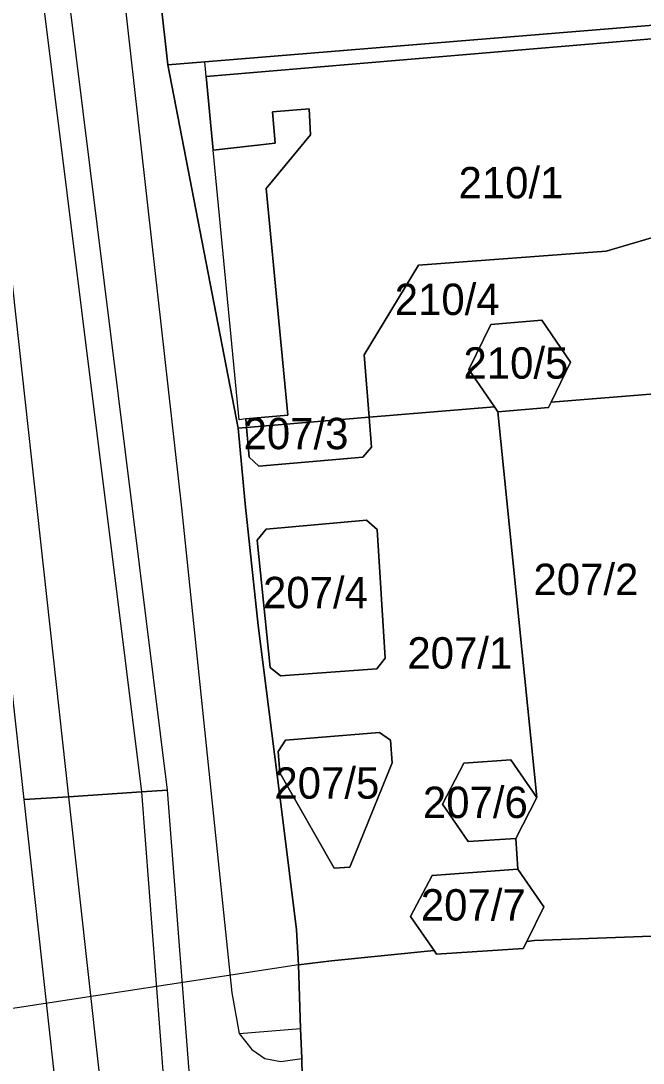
# Model space of a CAD drawing. Extents: x -263423 to -261326, y -1240067 to -1237864.
# Drawn here: x -263160.1 to -263120.4, y -1239967.1 to -1239900.6 of the extents above; entities that cross this region are included whole.
import ezdxf

# ---------------------------------------------------------------- set-up
doc = ezdxf.new("R2010")
doc.units = 0
for name, color, linetype in [('body_kn', 7, 'Continuous'), ('kladpar_druhypozemkov', 7, 'Continuous'), ('kladpar_hranice', 7, 'Continuous'), ('kladpar_parcelnecisla', 7, 'Continuous'), ('kladpar_plochy', 7, 'Continuous'), ('linie', 7, 'Continuous'), ('tarchy_linie', 7, 'Continuous'), ('zappar_hrandruhpozemk', 7, 'Continuous')]:
    doc.layers.add(name, color=color, linetype=linetype)

msp = doc.modelspace()

# ---------------------------------------------------------------- linework, layer by layer
at = {"layer": 'body_kn'}
for p, q in [((-263150.73, -1239903.4), (-263150.73, -1239903.4)), ((-263150.73, -1239903.4), (-263150.73, -1239903.4)), ((-263148.38, -1239903.21), (-263148.38, -1239903.21)), ((-263148.29, -1239904.14), (-263148.29, -1239904.14)), ((-263148.29, -1239904.14), (-263148.29, -1239904.14)), ((-263141.71, -1239906.2), (-263141.71, -1239906.2)), ((-263144.05, -1239906.4), (-263144.05, -1239906.4)), ((-263141.63, -1239907.86), (-263141.63, -1239907.86)), ((-263147.84, -1239908.83), (-263147.84, -1239908.83)), ((-263143.88, -1239908.39), (-263143.88, -1239908.39)), ((-263144.45, -1239911.29), (-263144.45, -1239911.29)), ((-263122.76, -1239915.27), (-263122.76, -1239915.27)), ((-263134.75, -1239916.18), (-263134.75, -1239916.18)), ((-263130.12, -1239919.95), (-263130.12, -1239919.95)), ((-263126.87, -1239919.67), (-263126.87, -1239919.67)), ((-263138.21, -1239921.88), (-263138.21, -1239921.88)), ((-263131.54, -1239922.83), (-263131.54, -1239922.83)), ((-263125.04, -1239922.35), (-263125.04, -1239922.35)), ((-263126.28, -1239924.91), (-263126.28, -1239924.91)), ((-263129.9, -1239925.21), (-263129.9, -1239925.21)), ((-263129.68, -1239925.52), (-263129.68, -1239925.52)), ((-263129.68, -1239925.52), (-263129.68, -1239925.52)), ((-263126.44, -1239925.26), (-263126.44, -1239925.26)), ((-263146.19, -1239926.04), (-263146.19, -1239926.04)), ((-263145.76, -1239925.98), (-263145.76, -1239925.98)), ((-263145.76, -1239925.98), (-263145.76, -1239925.98)), ((-263143.07, -1239925.74), (-263143.07, -1239925.74)), ((-263137.88, -1239925.87), (-263137.88, -1239925.87)), ((-263137.88, -1239925.87), (-263137.88, -1239925.87)), ((-263146.25, -1239926.56), (-263146.25, -1239926.56)), ((-263146.25, -1239926.56), (-263146.25, -1239926.56)), ((-263145.72, -1239926.52), (-263145.72, -1239926.52)), ((-263137.73, -1239927.77), (-263137.73, -1239927.77)), ((-263145.54, -1239928.42), (-263145.54, -1239928.42)), ((-263138.29, -1239928.41), (-263138.29, -1239928.41)), ((-263144.93, -1239928.99), (-263144.93, -1239928.99)), ((-263145.8, -1239931.39), (-263145.8, -1239931.39)), ((-263149.86, -1239931.65), (-263149.86, -1239931.65)), ((-263138.06, -1239932.44), (-263138.06, -1239932.44)), ((-263144.47, -1239933.01), (-263144.47, -1239933.01)), ((-263137.38, -1239933.02), (-263137.38, -1239933.02)), ((-263145.03, -1239933.7), (-263145.03, -1239933.7)), ((-263144.96, -1239939.15), (-263144.96, -1239939.15)), ((-263136.87, -1239941.24), (-263136.87, -1239941.24)), ((-263136.87, -1239941.24), (-263136.87, -1239941.24)), ((-263144.21, -1239941.83), (-263144.21, -1239941.83)), ((-263137.39, -1239941.92), (-263137.39, -1239941.92)), ((-263143.54, -1239942.37), (-263143.54, -1239942.37)), ((-263137.23, -1239945.98), (-263137.23, -1239945.98)), ((-263143.23, -1239946.46), (-263143.23, -1239946.46)), ((-263136.53, -1239946.46), (-263136.53, -1239946.46)), ((-263143.7, -1239947.18), (-263143.7, -1239947.18)), ((-263136.42, -1239947.91), (-263136.42, -1239947.91)), ((-263131.84, -1239947.94), (-263131.84, -1239947.94)), ((-263128.86, -1239947.72), (-263128.86, -1239947.72)), ((-263143.58, -1239948.55), (-263143.58, -1239948.55)), ((-263157.06, -1239950.07), (-263157.06, -1239950.07)), ((-263157.06, -1239950.07), (-263157.06, -1239950.07)), ((-263152.42, -1239949.77), (-263152.42, -1239949.77)), ((-263152.42, -1239949.77), (-263152.42, -1239949.77)), ((-263150.78, -1239949.66), (-263150.78, -1239949.66)), ((-263127.19, -1239950.13), (-263127.19, -1239950.13)), ((-263159.9, -1239950.26), (-263159.9, -1239950.26)), ((-263133.22, -1239950.55), (-263133.22, -1239950.55)), ((-263143.42, -1239951.37), (-263143.42, -1239951.37)), ((-263128.54, -1239952.74), (-263128.54, -1239952.74)), ((-263128.54, -1239952.74), (-263128.54, -1239952.74)), ((-263131.57, -1239952.92), (-263131.57, -1239952.92)), ((-263140.12, -1239954.63), (-263140.12, -1239954.63)), ((-263139.12, -1239954.57), (-263139.12, -1239954.57)), ((-263139.12, -1239954.57), (-263139.12, -1239954.57)), ((-263128.4, -1239954.7), (-263128.4, -1239954.7)), ((-263133.88, -1239955.09), (-263133.88, -1239955.09)), ((-263126.75, -1239957.09), (-263126.75, -1239957.09)), ((-263126.75, -1239957.09), (-263126.75, -1239957.09)), ((-263135.25, -1239957.71), (-263135.25, -1239957.71)), ((-263142.52, -1239958.56), (-263142.52, -1239958.56)), ((-263127.83, -1239959.3), (-263127.83, -1239959.3)), ((-263127.34, -1239959.25), (-263127.34, -1239959.25)), ((-263133.75, -1239959.88), (-263133.75, -1239959.88)), ((-263133.59, -1239960.12), (-263133.59, -1239960.12)), ((-263128.06, -1239959.75), (-263128.06, -1239959.75)), ((-263142.39, -1239960.79), (-263142.39, -1239960.79)), ((-263140.3, -1239960.53), (-263140.3, -1239960.53)), ((-263146.64, -1239962.57), (-263146.64, -1239962.57)), ((-263146.19, -1239965.18), (-263146.19, -1239965.18)), ((-263146.19, -1239965.18), (-263146.19, -1239965.18)), ((-263142.26, -1239964.86), (-263142.26, -1239964.86)), ((-263145.37, -1239966.2), (-263145.37, -1239966.2)), ((-263144.54, -1239966.77), (-263144.54, -1239966.77)), ((-263142.19, -1239966.77), (-263142.19, -1239966.77)), ((-263143.52, -1239966.96), (-263143.52, -1239966.96))]:
    msp.add_line(p, q, dxfattribs=at)
at = {"layer": 'kladpar_druhypozemkov'}
for p, q in [((-263128.82, -1239910.13), (-263128.82, -1239910.13)), ((-263132.19, -1239917.97), (-263132.19, -1239917.97)), ((-263128.51, -1239921.59), (-263128.51, -1239921.59)), ((-263141.62, -1239926.61), (-263141.62, -1239926.61)), ((-263123.27, -1239935.24), (-263123.27, -1239935.24)), ((-263140.81, -1239935.63), (-263140.81, -1239935.63)), ((-263131.75, -1239940.11), (-263131.75, -1239940.11)), ((-263140, -1239948.19), (-263140, -1239948.19)), ((-263130.59, -1239949.77), (-263130.59, -1239949.77)), ((-263130.77, -1239956.39), (-263130.77, -1239956.39))]:
    msp.add_line(p, q, dxfattribs=at)
at = {"layer": 'kladpar_hranice'}
for points in [[(-263160.1, -1239830.46), (-263160.09, -1239840), (-263159.96, -1239841.97), (-263159.77, -1239843.43), (-263157.36, -1239843.24), (-263154.97, -1239865.49), (-263150.73, -1239903.4), (-263146.25, -1239926.56), (-263145.8, -1239931.39), (-263144.96, -1239939.15), (-263143.42, -1239951.37), (-263142.52, -1239958.56), (-263142.39, -1239960.79), (-263142.26, -1239964.86), (-263142.19, -1239966.77), (-263141.99, -1239976.76)], [(-263109.71, -1239861.4), (-263104.15, -1239861.04), (-263104.09, -1239861.55), (-263103.51, -1239866.79), (-263103.48, -1239867.04), (-263117.01, -1239868.18), (-263116.53, -1239872.27), (-263114.41, -1239890.35), (-263113.94, -1239894.4), (-263113.26, -1239900.34), (-263148.38, -1239903.21), (-263150.73, -1239903.4), (-263154.97, -1239865.49), (-263140.37, -1239864.09), (-263109.71, -1239861.4)], [(-263150.73, -1239903.4), (-263148.38, -1239903.21), (-263113.26, -1239900.34)], [(-263113.57, -1239901.21), (-263148.29, -1239904.14), (-263147.84, -1239908.83), (-263143.88, -1239908.39), (-263144.05, -1239906.4), (-263141.71, -1239906.2), (-263141.63, -1239907.86), (-263144.45, -1239911.29), (-263143.07, -1239925.74), (-263145.76, -1239925.98), (-263145.72, -1239926.52), (-263146.25, -1239926.56), (-263150.73, -1239903.4)], [(-263137.88, -1239925.87), (-263145.72, -1239926.52), (-263145.76, -1239925.98), (-263143.07, -1239925.74), (-263144.45, -1239911.29), (-263141.63, -1239907.86), (-263141.71, -1239906.2), (-263144.05, -1239906.4), (-263143.88, -1239908.39), (-263147.84, -1239908.83), (-263148.29, -1239904.14), (-263113.57, -1239901.21), (-263113.38, -1239902.45), (-263113.51, -1239902.94), (-263119.88, -1239914.43), (-263122.76, -1239915.27), (-263134.75, -1239916.18), (-263138.21, -1239921.88), (-263137.88, -1239925.87)], [(-263119.15, -1239924.33), (-263126.28, -1239924.91), (-263125.04, -1239922.35), (-263126.87, -1239919.67), (-263130.12, -1239919.95), (-263131.54, -1239922.83), (-263129.9, -1239925.21), (-263137.88, -1239925.87), (-263138.21, -1239921.88), (-263134.75, -1239916.18), (-263122.76, -1239915.27), (-263119.88, -1239914.43)], [(-263129.68, -1239925.52), (-263129.9, -1239925.21), (-263131.54, -1239922.83), (-263130.12, -1239919.95), (-263126.87, -1239919.67), (-263125.04, -1239922.35), (-263126.28, -1239924.91), (-263126.44, -1239925.26), (-263129.68, -1239925.52)], [(-263107.84, -1239958.51), (-263127.34, -1239959.25), (-263127.83, -1239959.3), (-263126.75, -1239957.09), (-263128.4, -1239954.7), (-263128.54, -1239952.74), (-263127.19, -1239950.13), (-263129.68, -1239925.52), (-263126.44, -1239925.26), (-263126.28, -1239924.91), (-263119.15, -1239924.33)], [(-263146.25, -1239926.56), (-263145.72, -1239926.52), (-263145.54, -1239928.42), (-263144.93, -1239928.99), (-263138.29, -1239928.41), (-263137.73, -1239927.77), (-263137.88, -1239925.87), (-263129.9, -1239925.21), (-263129.68, -1239925.52), (-263127.19, -1239950.13), (-263128.86, -1239947.72), (-263131.84, -1239947.94), (-263133.22, -1239950.55), (-263131.57, -1239952.92), (-263128.54, -1239952.74), (-263128.4, -1239954.7), (-263133.88, -1239955.09), (-263135.25, -1239957.71), (-263133.75, -1239959.88), (-263140.3, -1239960.53), (-263142.39, -1239960.79), (-263142.52, -1239958.56)], [(-263137.88, -1239925.87), (-263137.73, -1239927.77), (-263138.29, -1239928.41), (-263144.93, -1239928.99), (-263145.54, -1239928.42), (-263145.72, -1239926.52), (-263137.88, -1239925.87)], [(-263144.96, -1239939.15), (-263145.8, -1239931.39), (-263146.25, -1239926.56)], [(-263136.87, -1239941.24), (-263137.39, -1239941.92), (-263143.54, -1239942.37), (-263144.21, -1239941.83), (-263145.03, -1239933.7), (-263144.47, -1239933.01), (-263138.06, -1239932.44), (-263137.38, -1239933.02), (-263136.87, -1239941.24)], [(-263144.21, -1239941.83), (-263143.54, -1239942.37), (-263137.39, -1239941.92), (-263136.87, -1239941.24), (-263137.38, -1239933.02), (-263138.06, -1239932.44), (-263144.47, -1239933.01), (-263145.03, -1239933.7), (-263144.21, -1239941.83)], [(-263142.52, -1239958.56), (-263143.42, -1239951.37), (-263144.96, -1239939.15)], [(-263139.12, -1239954.57), (-263140.12, -1239954.63), (-263143.58, -1239948.55), (-263143.7, -1239947.18), (-263143.23, -1239946.46), (-263137.23, -1239945.98), (-263136.53, -1239946.46), (-263136.42, -1239947.91), (-263139.12, -1239954.57)], [(-263139.12, -1239954.57), (-263136.42, -1239947.91), (-263136.53, -1239946.46), (-263137.23, -1239945.98), (-263143.23, -1239946.46), (-263143.7, -1239947.18), (-263143.58, -1239948.55), (-263140.12, -1239954.63), (-263139.12, -1239954.57)], [(-263128.54, -1239952.74), (-263131.57, -1239952.92), (-263133.22, -1239950.55), (-263131.84, -1239947.94), (-263128.86, -1239947.72), (-263127.19, -1239950.13), (-263128.54, -1239952.74)], [(-263126.75, -1239957.09), (-263127.83, -1239959.3), (-263128.06, -1239959.75), (-263133.59, -1239960.12), (-263133.75, -1239959.88), (-263135.25, -1239957.71), (-263133.88, -1239955.09), (-263128.4, -1239954.7), (-263126.75, -1239957.09)], [(-263141.99, -1239976.76), (-263142.19, -1239966.77), (-263142.26, -1239964.86), (-263142.39, -1239960.79), (-263140.3, -1239960.53), (-263133.75, -1239959.88), (-263133.59, -1239960.12), (-263128.06, -1239959.75), (-263127.83, -1239959.3), (-263127.34, -1239959.25), (-263107.84, -1239958.51), (-263088.3, -1239957.01)]]:
    msp.add_lwpolyline(points, dxfattribs=at)
at = {"layer": 'kladpar_plochy'}
for p, q in [((-263154.97, -1239865.49), (-263150.73, -1239903.4)), ((-263150.73, -1239903.4), (-263146.25, -1239926.56)), ((-263137.88, -1239925.87), (-263129.9, -1239925.21)), ((-263129.9, -1239925.21), (-263129.68, -1239925.52)), ((-263129.68, -1239925.52), (-263127.19, -1239950.13)), ((-263137.73, -1239927.77), (-263137.88, -1239925.87)), ((-263146.25, -1239926.56), (-263145.72, -1239926.52)), ((-263145.8, -1239931.39), (-263146.25, -1239926.56)), ((-263146.25, -1239926.56), (-263145.8, -1239931.39)), ((-263145.72, -1239926.52), (-263145.54, -1239928.42)), ((-263138.29, -1239928.41), (-263137.73, -1239927.77)), ((-263145.54, -1239928.42), (-263144.93, -1239928.99)), ((-263144.93, -1239928.99), (-263138.29, -1239928.41)), ((-263144.96, -1239939.15), (-263145.8, -1239931.39)), ((-263145.8, -1239931.39), (-263144.96, -1239939.15)), ((-263138.06, -1239932.44), (-263144.47, -1239933.01)), ((-263137.38, -1239933.02), (-263138.06, -1239932.44)), ((-263144.47, -1239933.01), (-263145.03, -1239933.7)), ((-263136.87, -1239941.24), (-263137.38, -1239933.02)), ((-263145.03, -1239933.7), (-263144.21, -1239941.83)), ((-263143.42, -1239951.37), (-263144.96, -1239939.15)), ((-263144.96, -1239939.15), (-263143.42, -1239951.37)), ((-263137.39, -1239941.92), (-263136.87, -1239941.24)), ((-263144.21, -1239941.83), (-263143.54, -1239942.37)), ((-263143.54, -1239942.37), (-263137.39, -1239941.92)), ((-263137.23, -1239945.98), (-263143.23, -1239946.46)), ((-263136.53, -1239946.46), (-263137.23, -1239945.98)), ((-263143.23, -1239946.46), (-263143.7, -1239947.18)), ((-263136.42, -1239947.91), (-263136.53, -1239946.46)), ((-263143.7, -1239947.18), (-263143.58, -1239948.55)), ((-263139.12, -1239954.57), (-263136.42, -1239947.91)), ((-263131.84, -1239947.94), (-263133.22, -1239950.55)), ((-263128.86, -1239947.72), (-263131.84, -1239947.94)), ((-263127.19, -1239950.13), (-263128.86, -1239947.72)), ((-263143.58, -1239948.55), (-263140.12, -1239954.63)), ((-263133.22, -1239950.55), (-263131.57, -1239952.92)), ((-263142.52, -1239958.56), (-263143.42, -1239951.37)), ((-263143.42, -1239951.37), (-263142.52, -1239958.56)), ((-263131.57, -1239952.92), (-263128.54, -1239952.74)), ((-263128.54, -1239952.74), (-263128.4, -1239954.7)), ((-263140.12, -1239954.63), (-263139.12, -1239954.57)), ((-263128.4, -1239954.7), (-263133.88, -1239955.09)), ((-263133.88, -1239955.09), (-263135.25, -1239957.71)), ((-263135.25, -1239957.71), (-263133.75, -1239959.88)), ((-263142.39, -1239960.79), (-263142.52, -1239958.56)), ((-263142.52, -1239958.56), (-263142.39, -1239960.79)), ((-263133.75, -1239959.88), (-263140.3, -1239960.53)), ((-263140.3, -1239960.53), (-263142.39, -1239960.79)), ((-263142.39, -1239960.79), (-263142.26, -1239964.86)), ((-263142.26, -1239964.86), (-263142.19, -1239966.77)), ((-263142.19, -1239966.77), (-263141.99, -1239976.76))]:
    msp.add_line(p, q, dxfattribs=at)
for points in [[(-263109.71, -1239861.4), (-263104.15, -1239861.04), (-263104.09, -1239861.55), (-263103.51, -1239866.79), (-263103.48, -1239867.04), (-263117.01, -1239868.18), (-263116.53, -1239872.27), (-263114.41, -1239890.35), (-263113.94, -1239894.4), (-263113.26, -1239900.34), (-263148.38, -1239903.21), (-263150.73, -1239903.4), (-263154.97, -1239865.49), (-263140.37, -1239864.09)], [(-263137.88, -1239925.87), (-263145.72, -1239926.52), (-263145.76, -1239925.98), (-263143.07, -1239925.74), (-263144.45, -1239911.29), (-263141.63, -1239907.86), (-263141.71, -1239906.2), (-263144.05, -1239906.4), (-263143.88, -1239908.39), (-263147.84, -1239908.83), (-263148.29, -1239904.14), (-263113.57, -1239901.21), (-263113.38, -1239902.45), (-263113.51, -1239902.94), (-263119.88, -1239914.43), (-263122.76, -1239915.27), (-263134.75, -1239916.18), (-263138.21, -1239921.88)], [(-263129.68, -1239925.52), (-263129.9, -1239925.21), (-263131.54, -1239922.83), (-263130.12, -1239919.95), (-263126.87, -1239919.67), (-263125.04, -1239922.35), (-263126.28, -1239924.91), (-263126.44, -1239925.26)], [(-263137.88, -1239925.87), (-263137.73, -1239927.77), (-263138.29, -1239928.41), (-263144.93, -1239928.99), (-263145.54, -1239928.42), (-263145.72, -1239926.52)], [(-263136.87, -1239941.24), (-263137.39, -1239941.92), (-263143.54, -1239942.37), (-263144.21, -1239941.83), (-263145.03, -1239933.7), (-263144.47, -1239933.01), (-263138.06, -1239932.44), (-263137.38, -1239933.02)], [(-263139.12, -1239954.57), (-263140.12, -1239954.63), (-263143.58, -1239948.55), (-263143.7, -1239947.18), (-263143.23, -1239946.46), (-263137.23, -1239945.98), (-263136.53, -1239946.46), (-263136.42, -1239947.91)], [(-263128.54, -1239952.74), (-263131.57, -1239952.92), (-263133.22, -1239950.55), (-263131.84, -1239947.94), (-263128.86, -1239947.72), (-263127.19, -1239950.13)], [(-263126.75, -1239957.09), (-263127.83, -1239959.3), (-263128.06, -1239959.75), (-263133.59, -1239960.12), (-263133.75, -1239959.88), (-263135.25, -1239957.71), (-263133.88, -1239955.09), (-263128.4, -1239954.7)]]:
    msp.add_lwpolyline(points, close=True, dxfattribs=at)
for points in [[(-263113.57, -1239901.21), (-263148.29, -1239904.14), (-263147.84, -1239908.83), (-263143.88, -1239908.39), (-263144.05, -1239906.4), (-263141.71, -1239906.2), (-263141.63, -1239907.86), (-263144.45, -1239911.29), (-263143.07, -1239925.74), (-263145.76, -1239925.98), (-263145.72, -1239926.52), (-263146.25, -1239926.56), (-263150.73, -1239903.4), (-263148.38, -1239903.21), (-263113.26, -1239900.34)], [(-263119.15, -1239924.33), (-263126.28, -1239924.91), (-263125.04, -1239922.35), (-263126.87, -1239919.67), (-263130.12, -1239919.95), (-263131.54, -1239922.83), (-263129.9, -1239925.21), (-263137.88, -1239925.87), (-263138.21, -1239921.88), (-263134.75, -1239916.18), (-263122.76, -1239915.27), (-263119.88, -1239914.43)], [(-263107.84, -1239958.51), (-263127.34, -1239959.25), (-263127.83, -1239959.3), (-263126.75, -1239957.09), (-263128.4, -1239954.7), (-263128.54, -1239952.74), (-263127.19, -1239950.13), (-263129.68, -1239925.52), (-263126.44, -1239925.26), (-263126.28, -1239924.91), (-263119.15, -1239924.33)], [(-263141.99, -1239976.76), (-263142.19, -1239966.77), (-263142.26, -1239964.86), (-263142.39, -1239960.79), (-263140.3, -1239960.53), (-263133.75, -1239959.88), (-263133.59, -1239960.12), (-263128.06, -1239959.75), (-263127.83, -1239959.3), (-263127.34, -1239959.25), (-263107.84, -1239958.51), (-263088.3, -1239957.01), (-263088.24, -1239957.71), (-263083.2, -1239957.36), (-263083.2, -1239956.78), (-263078.79, -1239956.48)]]:
    msp.add_lwpolyline(points, dxfattribs=at)
at = {"layer": 'linie'}
msp.add_lwpolyline([(-263078.79, -1239956.48), (-263083.2, -1239956.78), (-263083.2, -1239957.36), (-263088.24, -1239957.71), (-263088.3, -1239957.01), (-263107.84, -1239958.51), (-263127.34, -1239959.25), (-263127.83, -1239959.3), (-263128.06, -1239959.75), (-263133.59, -1239960.12), (-263133.75, -1239959.88), (-263140.3, -1239960.53), (-263142.39, -1239960.79), (-263161.9, -1239963.77)], dxfattribs=at)
at = {"layer": 'tarchy_linie'}
for points in [[(-263185.2, -1239701.74), (-263177.2, -1239769.3), (-263169.7, -1239837.34), (-263162.04, -1239904.96), (-263157.06, -1239950.07)], [(-263179.52, -1239701.91), (-263177.35, -1239723.64), (-263164.61, -1239831.56), (-263160.93, -1239881.34), (-263152.42, -1239949.77)], [(-263160.13, -1239831.12), (-263160.13, -1239832.68), (-263162.85, -1239832.94), (-263162.7, -1239835.06), (-263160.13, -1239834.82), (-263160.12, -1239836.48), (-263160.12, -1239838.14), (-263162.45, -1239838.36), (-263159.29, -1239881.2), (-263150.78, -1239949.66), (-263152.42, -1239949.77), (-263157.06, -1239950.07), (-263159.9, -1239950.26), (-263164.87, -1239905.28), (-263172.53, -1239837.66), (-263180.03, -1239769.62)], [(-263190.37, -1239978.1), (-263157.01, -1239977.05), (-263157.34, -1239973.44), (-263159.9, -1239950.26), (-263157.06, -1239950.07), (-263152.42, -1239949.77), (-263150.78, -1239949.66), (-263149.14, -1239970.88), (-263142.12, -1239970.1), (-263142.09, -1239971.76), (-263142.06, -1239973.41), (-263148.89, -1239974.17), (-263148.78, -1239975.59), (-263142.03, -1239974.81), (-263142, -1239976.35), (-263141.99, -1239976.76), (-263141.95, -1239977.89), (-263148.45, -1239978.65), (-263146.13, -1239993.5), (-263145.84, -1239995.36), (-263032.56, -1240009.33)], [(-263157.06, -1239950.07), (-263154.51, -1239973.13), (-263150.79, -1240013.01)], [(-263152.42, -1239949.77), (-263150.3, -1239977.32), (-263150.15, -1239978.44), (-263147.76, -1239993.75), (-263147.28, -1239996.85), (-263143.48, -1240031.07)]]:
    msp.add_lwpolyline(points, dxfattribs=at)
at = {"layer": 'zappar_hrandruhpozemk'}
for p, q in [((-263155.33, -1239882.92), (-263149.86, -1239931.65)), ((-263148.29, -1239904.14), (-263148.38, -1239903.21)), ((-263146.19, -1239926.04), (-263147.84, -1239908.83)), ((-263145.76, -1239925.98), (-263146.19, -1239926.04)), ((-263146.19, -1239965.18), (-263142.26, -1239964.86))]:
    msp.add_line(p, q, dxfattribs=at)
msp.add_lwpolyline([(-263149.86, -1239931.65), (-263146.64, -1239962.57), (-263146.19, -1239965.18), (-263145.37, -1239966.2), (-263144.54, -1239966.77), (-263143.52, -1239966.96), (-263142.19, -1239966.77)], dxfattribs=at)

# ---------------------------------------------------------------- texts
at = {"layer": 'kladpar_parcelnecisla'}
for s, p in [('210/1', (-263132.188, -1239911.91)), ('210/4', (-263136.258, -1239919.35)), ('210/5', (-263131.873, -1239923.41)), ('207/3', (-263145.902, -1239927.91)), ('207/2', (-263127.407, -1239937.21)), ('207/4', (-263144.66, -1239938.05)), ('207/1', (-263135.45, -1239941.9)), ('207/5', (-263143.935, -1239950.2)), ('207/6', (-263134.46, -1239951.43)), ('207/7', (-263134.593, -1239957.97))]:
    msp.add_text(s, height=2, dxfattribs=at).set_placement(p)

doc.saveas('drawing.dxf')
